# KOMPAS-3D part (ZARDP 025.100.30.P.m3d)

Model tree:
1. Плоскость XY
2. Плоскость ZX
3. Плоскость ZY
4. Ось X
5. Ось Y
6. Ось Z
7. Начало координат
8. Булева операция:1
9. Булева операция:2
10. Булева операция:3
11. Булева операция:4
12. Булева операция:5
13. Булева операция:6
